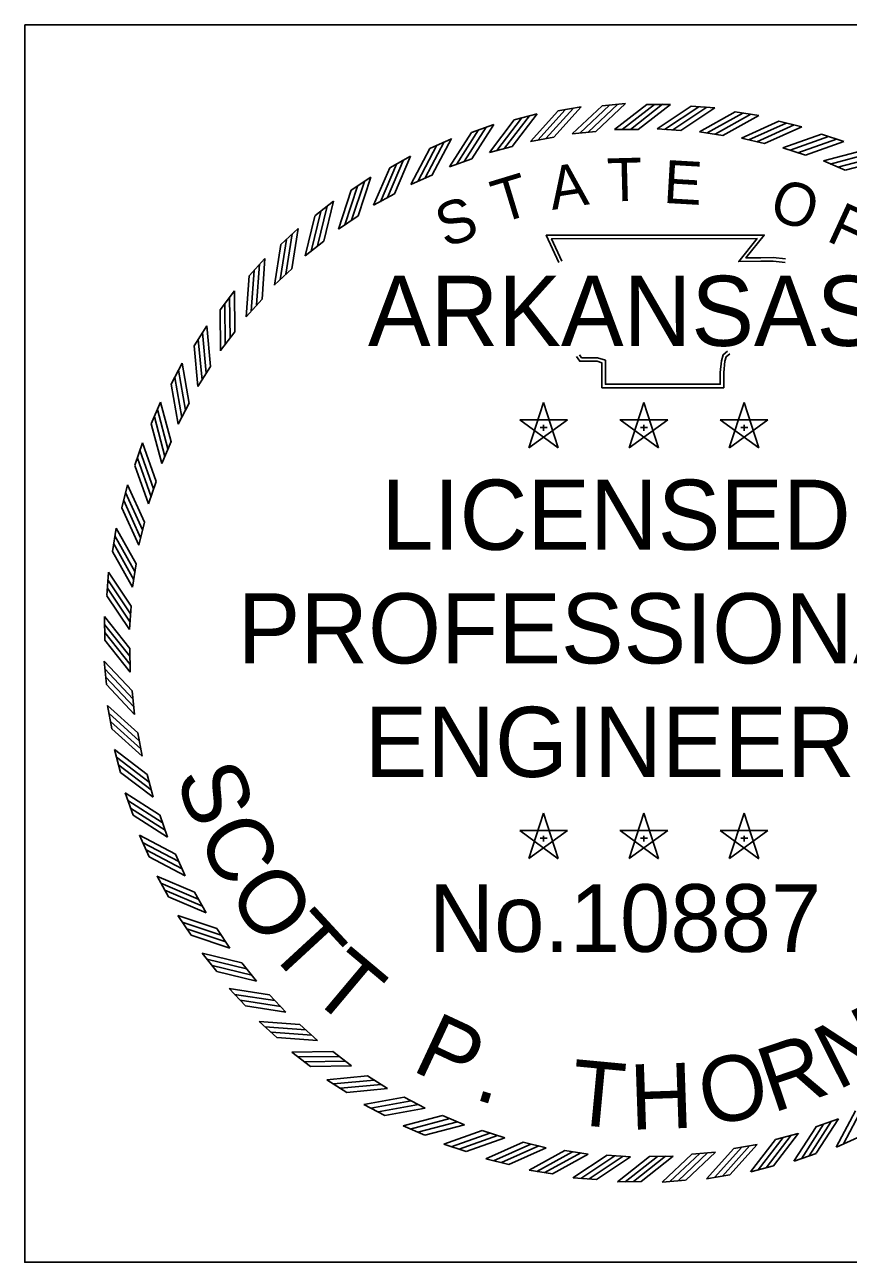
# Model space of a CAD drawing. Extents: x 164 to 3385, y 68 to 2119.
# Drawn here: x 3004.1 to 3177.5, y 441.7 to 702.4 of the extents above; entities that cross this region are included whole.
import ezdxf

# ---------------------------------------------------------------- set-up
doc = ezdxf.new("R2010")
doc.units = 0
doc.layers.add('R_No Plot', color=7, linetype='Continuous')
doc.layers.add('STAMP', color=7, linetype='Continuous')

msp = doc.modelspace()

# ---------------------------------------------------------------- linework, layer by layer
at = {"layer": 'R_No Plot'}
msp.add_lwpolyline([(3004.12, 702.45), (3264.86, 702.45), (3264.86, 441.7), (3004.12, 441.7)], close=True, dxfattribs=at)
at = {"layer": 'STAMP'}
for p, q in [((3125.7, 685.39), (3130.65, 685.85)), ((3107.19, 682.4), (3112, 683.67)), ((3116.38, 684.28), (3121.28, 685.14)), ((3135.12, 685.67), (3140.1, 685.67)), ((3144.45, 685.3), (3149.42, 684.94)), ((3144.45, 685.3), (3149.41, 684.93)), ((3153.75, 684.09), (3158.67, 683.31)), ((3098.18, 679.77), (3102.87, 681.43)), ((3162.93, 682.12), (3167.76, 680.94)), ((3089.42, 676.4), (3093.96, 678.44)), ((3110.61, 677.88), (3115.52, 678.75)), ((3119.42, 679.49), (3124.39, 679.95)), ((3128.33, 680.37), (3133.32, 680.37)), ((3137.28, 680.51), (3142.26, 680.15)), ((3137.28, 680.51), (3142.26, 680.15)), ((3146.22, 679.91), (3151.15, 679.14)), ((3155.07, 678.58), (3159.92, 677.4)), ((3171.9, 679.39), (3176.63, 677.82)), ((3101.97, 675.55), (3106.79, 676.82)), ((3163.79, 676.51), (3168.52, 674.94)), ((3080.97, 672.33), (3085.33, 674.73)), ((3093.54, 672.51), (3098.25, 674.17)), ((3172.3, 673.74), (3176.89, 671.78)), ((3072.89, 667.56), (3077.03, 670.32)), ((3085.4, 668.79), (3089.95, 670.83)), ((3065.22, 662.15), (3069.12, 665.24)), ((3077.59, 664.4), (3081.96, 666.82)), ((3070.17, 659.39), (3074.32, 662.16)), ((3058.03, 656.12), (3061.66, 659.53)), ((3063.19, 653.78), (3067.1, 656.88)), ((3051.36, 649.52), (3054.7, 653.21)), ((3056.7, 647.61), (3060.34, 651.02)), ((3045.26, 642.39), (3048.28, 646.35)), ((3050.74, 640.93), (3054.08, 644.63)), ((3039.77, 634.78), (3042.46, 638.98)), ((3045.35, 633.78), (3048.38, 637.74)), ((3034.93, 626.75), (3037.26, 631.15)), ((3040.57, 626.21), (3043.26, 630.41)), ((3030.76, 618.34), (3032.72, 622.92)), ((3036.43, 618.27), (3038.76, 622.68)), ((3113.37, 622.87), (3110.26, 613.31)), ((3116.47, 613.32), (3113.38, 622.88)), ((3134.49, 622.87), (3131.37, 613.31)), ((3137.59, 613.32), (3134.49, 622.88)), ((3155.6, 622.87), (3152.48, 613.31)), ((3158.7, 613.32), (3155.61, 622.88)), ((3118.39, 619.22), (3108.34, 619.23)), ((3108.35, 619.22), (3116.48, 613.3)), ((3110.27, 613.32), (3118.4, 619.22)), ((3113.38, 618.15), (3113.38, 616.89)), ((3139.51, 619.22), (3129.46, 619.23)), ((3129.47, 619.22), (3137.59, 613.3)), ((3131.38, 613.32), (3139.52, 619.22)), ((3134.49, 618.15), (3134.49, 616.89)), ((3160.62, 619.22), (3150.57, 619.23)), ((3150.58, 619.22), (3158.7, 613.3)), ((3152.5, 613.32), (3160.63, 619.22)), ((3155.61, 618.15), (3155.61, 616.89)), ((3112.66, 617.61), (3114.15, 617.61)), ((3133.77, 617.61), (3135.26, 617.61)), ((3154.88, 617.61), (3156.38, 617.61)), ((3027.31, 609.62), (3028.88, 614.34)), ((3032.96, 610.01), (3034.92, 614.6)), ((3024.58, 600.64), (3025.76, 605.47)), ((3030.19, 601.5), (3031.76, 606.23)), ((3028.12, 592.78), (3029.3, 597.63)), ((3022.61, 591.46), (3023.39, 596.38)), ((3021.4, 582.16), (3021.77, 587.12)), ((3026.79, 583.93), (3027.56, 588.86)), ((3026.19, 574.99), (3026.55, 579.97)), ((3020.97, 572.79), (3020.92, 577.76)), ((3026.33, 566.04), (3026.28, 571.03)), ((3021.31, 563.41), (3020.85, 568.36)), ((3027.21, 557.13), (3026.75, 562.1)), ((3022.42, 554.09), (3021.56, 558.99)), ((3028.82, 548.32), (3027.95, 553.24)), ((3024.3, 544.9), (3023.03, 549.71)), ((3031.15, 539.68), (3029.88, 544.5)), ((3026.93, 535.89), (3025.27, 540.58)), ((3034.19, 531.25), (3032.53, 535.96)), ((3113.37, 536.29), (3110.26, 526.74)), ((3116.47, 526.75), (3113.38, 536.31)), ((3134.49, 536.29), (3131.37, 526.74)), ((3137.59, 526.75), (3134.49, 536.31)), ((3155.6, 536.29), (3152.48, 526.74)), ((3158.7, 526.75), (3155.61, 536.31)), ((3118.39, 532.65), (3108.34, 532.66)), ((3108.35, 532.65), (3116.48, 526.73)), ((3110.27, 526.75), (3118.4, 532.64)), ((3139.51, 532.65), (3129.46, 532.66)), ((3129.47, 532.65), (3137.59, 526.73)), ((3131.38, 526.75), (3139.52, 532.64)), ((3160.62, 532.65), (3150.57, 532.66)), ((3150.58, 532.65), (3158.7, 526.73)), ((3152.5, 526.75), (3160.63, 532.64)), ((3030.3, 527.13), (3028.26, 531.67)), ((3112.66, 531.04), (3114.15, 531.04)), ((3113.38, 531.58), (3113.38, 530.32)), ((3133.77, 531.04), (3135.26, 531.04)), ((3134.49, 531.58), (3134.49, 530.32)), ((3154.88, 531.04), (3156.38, 531.04)), ((3155.61, 531.58), (3155.61, 530.32)), ((3037.91, 523.11), (3035.87, 527.66)), ((3034.38, 518.68), (3031.97, 523.04)), ((3042.3, 515.3), (3039.88, 519.67)), ((3039.14, 510.6), (3036.38, 514.74)), ((3047.31, 507.88), (3044.55, 512.03)), ((3044.55, 502.93), (3041.46, 506.83)), ((3052.92, 500.9), (3049.82, 504.81)), ((3050.58, 495.74), (3047.17, 499.37)), ((3059.09, 494.41), (3055.68, 498.05)), ((3057.18, 489.07), (3053.49, 492.41)), ((3065.77, 488.45), (3062.07, 491.79)), ((3064.31, 482.97), (3060.35, 485.99)), ((3072.92, 483.06), (3068.96, 486.09)), ((3071.92, 477.48), (3067.72, 480.17)), ((3080.49, 478.28), (3076.29, 480.97)), ((3079.95, 472.64), (3075.55, 474.97)), ((3088.43, 474.14), (3084.02, 476.48)), ((3096.69, 470.67), (3092.1, 472.63)), ((3088.36, 468.47), (3083.78, 470.43)), ((3105.2, 467.9), (3100.47, 469.47)), ((3175.45, 471.9), (3170.74, 470.24)), ((3113.92, 465.84), (3109.07, 467.02)), ((3167.02, 468.86), (3162.2, 467.59)), ((3179.57, 468.01), (3175.03, 465.97)), ((3097.08, 465.02), (3092.36, 466.59)), ((3122.77, 464.5), (3117.84, 465.28)), ((3131.71, 463.9), (3126.73, 464.27)), ((3149.57, 464.92), (3144.6, 464.46)), ((3158.38, 466.53), (3153.47, 465.66)), ((3170.81, 464.64), (3166.12, 462.98)), ((3106.06, 462.3), (3101.23, 463.47)), ((3140.66, 464.04), (3135.67, 463.99)), ((3161.8, 462.01), (3156.99, 460.74)), ((3115.24, 460.32), (3110.32, 461.1)), ((3124.54, 459.12), (3119.58, 459.48)), ((3143.29, 459.02), (3138.34, 458.56)), ((3152.61, 460.13), (3147.71, 459.27)), ((3133.92, 458.68), (3128.94, 458.63))]:
    msp.add_line(p, q, dxfattribs=at)
for points in [[(3124.38, 679.96), (3130.66, 685.85)], [(3105.18, 676.41), (3110.4, 683.26)], [(3106.78, 676.82), (3112, 683.67)], [(3110.61, 677.88), (3116.37, 684.27)], [(3112.19, 678.14), (3117.95, 684.54)], [(3113.88, 678.48), (3119.65, 684.88)], [(3115.52, 678.75), (3121.29, 685.15)], [(3119.41, 679.49), (3125.69, 685.39)], [(3121.01, 679.62), (3127.29, 685.52)], [(3122.73, 679.82), (3129.01, 685.72)], [(3128.32, 680.37), (3135.12, 685.67)], [(3129.93, 680.35), (3136.72, 685.65)], [(3131.66, 680.39), (3138.45, 685.69)], [(3133.31, 680.38), (3140.11, 685.67)], [(3137.27, 680.51), (3144.44, 685.3)], [(3137.28, 680.51), (3144.44, 685.29)], [(3138.87, 680.38), (3146.04, 685.17)], [(3138.87, 680.38), (3146.04, 685.16)], [(3140.6, 680.29), (3147.77, 685.08)], [(3140.6, 680.29), (3147.76, 685.07)], [(3142.25, 680.15), (3149.42, 684.94)], [(3142.25, 680.15), (3149.42, 684.93)], [(3146.21, 679.91), (3153.74, 684.09)], [(3147.79, 679.65), (3155.32, 683.82)], [(3149.51, 679.41), (3157.04, 683.59)], [(3151.14, 679.14), (3158.67, 683.32)], [(3096.67, 673.64), (3101.31, 680.9)], [(3098.24, 674.18), (3102.88, 681.43)], [(3101.96, 675.54), (3107.18, 682.39)], [(3103.51, 675.94), (3108.73, 682.79)], [(3155.07, 678.57), (3162.92, 682.11)], [(3156.62, 678.18), (3164.47, 681.72)], [(3158.31, 677.81), (3166.16, 681.35)], [(3159.92, 677.4), (3167.77, 680.94)], [(3089.94, 670.83), (3093.96, 678.45)], [(3093.54, 672.5), (3098.18, 679.76)], [(3095.05, 673.02), (3099.69, 680.28)], [(3163.78, 676.51), (3171.9, 679.39)], [(3165.29, 675.99), (3173.41, 678.87)], [(3166.95, 675.48), (3175.06, 678.36)], [(3085.4, 668.78), (3089.42, 676.4)], [(3086.86, 669.42), (3090.88, 677.04)], [(3088.42, 670.17), (3092.45, 677.78)], [(3168.52, 674.94), (3176.63, 677.82)], [(3172.29, 673.74), (3180.62, 675.94)], [(3079, 665.16), (3082.38, 673.08)], [(3080.49, 666.03), (3083.87, 673.95)], [(3081.95, 666.82), (3085.33, 674.74)], [(3173.76, 673.09), (3182.09, 675.29)], [(3175.36, 672.45), (3183.69, 674.65)], [(3176.88, 671.78), (3185.21, 673.98)], [(3074.32, 662.16), (3077.03, 670.33)], [(3077.59, 664.4), (3080.97, 672.32)], [(3070.17, 659.38), (3072.88, 667.56)], [(3071.51, 660.26), (3074.22, 668.43)], [(3072.93, 661.25), (3075.64, 669.42)], [(3067.09, 656.88), (3069.12, 665.25)], [(3064.45, 654.76), (3066.48, 663.13)], [(3065.79, 655.86), (3067.81, 664.23)], [(3063.19, 653.77), (3065.22, 662.14)], [(3057.88, 648.69), (3059.21, 657.2)], [(3059.11, 649.9), (3060.44, 658.41)], [(3060.33, 651.02), (3061.66, 659.53)], [(3116.58, 652.36), (3113.92, 658.1), (3159.83, 658.13), (3156, 653.31), (3159.11, 653.35), (3161.72, 653.38), (3164.32, 653.1)], [(3117.24, 652.66), (3115.06, 657.37), (3158.32, 657.4), (3154.47, 652.56), (3159.12, 652.62), (3161.69, 652.66), (3164.24, 652.38)], [(3056.7, 647.6), (3058.03, 656.11)], [(3052.95, 643.41), (3053.58, 652)], [(3054.08, 644.63), (3054.7, 653.22)], [(3050.74, 640.92), (3051.36, 649.51)], [(3051.82, 642.1), (3052.45, 650.69)], [(3047.35, 636.43), (3047.26, 645.05)], [(3048.37, 637.74), (3048.28, 646.35)], [(3045.35, 633.77), (3045.26, 642.38)], [(3046.33, 635.04), (3046.25, 643.65)], [(3043.25, 630.41), (3042.45, 638.98)], [(3042.35, 629.02), (3041.55, 637.59)], [(3040.57, 626.2), (3039.77, 634.78)], [(3041.45, 627.54), (3040.65, 636.12)], [(3152.14, 633.68), (3151.18, 632.9), (3150.84, 631.66), (3150.57, 629.19), (3150.57, 626.7), (3126.4, 626.7), (3126.4, 630.26), (3126.4, 631.75), (3124.74, 632.25), (3121.38, 632.25), (3120.94, 632.91)], [(3038.76, 622.67), (3037.25, 631.15)], [(3152.6, 633.12), (3151.82, 632.48), (3151.56, 631.53), (3151.3, 629.15), (3151.3, 625.97), (3125.67, 625.97), (3125.67, 630.26), (3125.67, 631.21), (3124.63, 631.53), (3120.98, 631.53), (3120.34, 632.52)], [(3037.97, 621.21), (3036.47, 629.69)], [(3036.43, 618.26), (3034.93, 626.74)], [(3037.19, 619.67), (3035.69, 628.15)], [(3034.25, 613.08), (3032.05, 621.4)], [(3034.92, 614.59), (3032.72, 622.92)], [(3032.96, 610), (3030.76, 618.33)], [(3033.61, 611.47), (3031.41, 619.8)], [(3031.22, 604.66), (3028.34, 612.78)], [(3031.76, 606.23), (3028.88, 614.34)], [(3030.71, 603.01), (3027.83, 611.12)], [(3030.19, 601.49), (3027.31, 609.61)], [(3029.3, 597.63), (3025.76, 605.48)], [(3028.89, 596.02), (3025.35, 603.87)], [(3028.13, 592.78), (3024.59, 600.63)], [(3028.52, 594.33), (3024.98, 602.18)], [(3027.29, 587.22), (3023.11, 594.75)], [(3027.56, 588.85), (3023.38, 596.39)], [(3027.06, 585.5), (3022.88, 593.04)], [(3026.79, 583.92), (3022.62, 591.46)], [(3026.55, 579.97), (3021.77, 587.13)], [(3026.41, 578.31), (3021.63, 585.47)], [(3026.19, 574.99), (3021.41, 582.15)], [(3026.32, 576.59), (3021.54, 583.75)], [(3026.28, 571.02), (3020.92, 577.77)], [(3026.28, 569.37), (3020.92, 576.11)], [(3026.33, 567.64), (3020.97, 574.38)], [(3026.33, 566.04), (3020.97, 572.78)], [(3026.75, 562.09), (3020.85, 568.37)], [(3026.88, 560.44), (3020.98, 566.72)], [(3027.08, 558.72), (3021.18, 565)], [(3027.21, 557.12), (3021.31, 563.4)], [(3027.95, 553.23), (3021.55, 559)], [(3028.22, 551.59), (3021.83, 557.36)], [(3028.56, 549.9), (3022.16, 555.67)], [(3028.82, 548.32), (3022.43, 554.09)], [(3029.88, 544.5), (3023.03, 549.72)], [(3030.29, 542.89), (3023.44, 548.11)], [(3030.76, 541.23), (3023.91, 546.45)], [(3031.16, 539.67), (3024.31, 544.89)], [(3032.52, 535.95), (3025.27, 540.59)], [(3033.06, 534.38), (3025.81, 539.02)], [(3033.68, 532.76), (3026.42, 537.4)], [(3034.2, 531.25), (3026.94, 535.89)], [(3035.87, 527.65), (3028.25, 531.68)], [(3036.53, 526.14), (3028.92, 530.16)], [(3037.28, 524.57), (3029.66, 528.6)], [(3037.92, 523.11), (3030.3, 527.13)], [(3039.88, 519.66), (3031.96, 523.04)], [(3040.67, 518.2), (3032.75, 521.58)], [(3041.54, 516.71), (3033.62, 520.09)], [(3042.31, 515.3), (3034.38, 518.68)], [(3044.55, 512.03), (3036.37, 514.74)], [(3045.45, 510.64), (3037.28, 513.35)], [(3046.44, 509.22), (3038.27, 511.94)], [(3047.32, 507.88), (3039.15, 510.59)], [(3049.82, 504.81), (3041.45, 506.83)], [(3050.84, 503.5), (3042.47, 505.53)], [(3051.95, 502.17), (3043.57, 504.2)], [(3052.93, 500.9), (3044.56, 502.93)], [(3055.68, 498.04), (3047.17, 499.37)], [(3056.8, 496.82), (3048.29, 498.15)], [(3058.01, 495.59), (3049.5, 496.92)], [(3059.1, 494.41), (3050.59, 495.74)], [(3062.07, 491.79), (3053.48, 492.41)], [(3063.29, 490.67), (3054.7, 491.29)], [(3064.6, 489.53), (3056.01, 490.16)], [(3065.78, 488.45), (3057.19, 489.07)], [(3068.96, 486.08), (3060.35, 485.99)], [(3070.27, 485.06), (3061.65, 484.98)], [(3071.66, 484.04), (3063.05, 483.96)], [(3072.93, 483.06), (3064.32, 482.97)], [(3076.29, 480.96), (3067.72, 480.17)], [(3077.68, 480.06), (3069.11, 479.26)], [(3079.16, 479.16), (3070.58, 478.36)], [(3080.5, 478.28), (3071.93, 477.48)], [(3084.03, 476.47), (3075.55, 474.97)], [(3085.49, 475.68), (3077.01, 474.18)], [(3087.03, 474.91), (3078.55, 473.4)], [(3088.44, 474.14), (3079.96, 472.64)], [(3092.11, 472.63), (3083.78, 470.43)], [(3093.62, 471.96), (3085.3, 469.76)], [(3179.05, 473.58), (3175.02, 465.96)], [(3180.57, 474.24), (3176.54, 466.63)], [(3095.23, 471.32), (3086.9, 469.12)], [(3096.7, 470.67), (3088.37, 468.48)], [(3100.47, 469.47), (3092.36, 466.59)], [(3170.75, 470.24), (3166.11, 462.98)], [(3172.32, 470.77), (3167.68, 463.52)], [(3173.94, 471.39), (3169.3, 464.13)], [(3175.45, 471.91), (3170.81, 464.65)], [(3102.04, 468.93), (3093.93, 466.05)], [(3103.69, 468.42), (3095.58, 465.54)], [(3105.21, 467.9), (3097.09, 465.02)], [(3109.07, 467.01), (3101.22, 463.47)], [(3162.21, 467.59), (3156.98, 460.74)], [(3163.81, 468), (3158.59, 461.15)], [(3165.48, 468.47), (3160.25, 461.62)], [(3167.03, 468.87), (3161.81, 462.02)], [(3110.68, 466.6), (3102.83, 463.06)], [(3112.37, 466.23), (3104.52, 462.69)], [(3113.92, 465.84), (3106.07, 462.3)], [(3117.85, 465.27), (3110.32, 461.09)], [(3119.48, 465), (3111.95, 460.82)], [(3121.2, 464.77), (3113.66, 460.59)], [(3122.78, 464.5), (3115.25, 460.33)], [(3126.74, 464.26), (3119.57, 459.48)], [(3144.61, 464.46), (3138.33, 458.56)], [(3146.26, 464.59), (3139.98, 458.7)], [(3147.98, 464.79), (3141.7, 458.89)], [(3149.58, 464.92), (3143.3, 459.02)], [(3153.47, 465.66), (3147.7, 459.26)], [(3155.11, 465.93), (3149.34, 459.54)], [(3156.8, 466.27), (3151.04, 459.87)], [(3158.38, 466.53), (3152.62, 460.14)], [(3128.39, 464.12), (3121.23, 459.34)], [(3130.12, 464.04), (3122.95, 459.25)], [(3131.71, 463.9), (3124.55, 459.12)], [(3135.68, 463.99), (3128.93, 458.63)], [(3137.33, 463.99), (3130.59, 458.63)], [(3139.06, 464.04), (3132.32, 458.68)], [(3140.66, 464.04), (3133.92, 458.68)]]:
    msp.add_lwpolyline(points, dxfattribs=at)

# ---------------------------------------------------------------- texts
for s, height, rotation, p in [('A', 9.06, 8.6788, (3115.18, 663.41)), ('T', 9.07, 1.4789, (3126.85, 665.19)), ('T', 9.06, 1.4789, (3126.87, 665.21)), ('E', 9.06, 356.672, (3138.46, 664.93)), ('T', 9.06, 16.9015, (3104.18, 660.54)), ('O', 9.06, 341.2218, (3160.45, 661.83)), ('S', 9.06, 19.7726, (3092.67, 655.37)), ('F', 9.06, 335.3628, (3172.65, 657.06)), ('S', 13.75, 289.7007, (3035.77, 544.11)), ('C', 13.75, 296.9967, (3040.19, 531.76)), ('O', 13.75, 304.6575, (3046.48, 519.51)), ('T', 13.75, 312.6831, (3054.76, 507.7)), ('T', 13.75, 319.9791, (3063.65, 498.06)), ('P', 13.75, 334.9359, (3085.31, 482.22)), ('N', 13.75, 26.7376, (3175.25, 477.81)), ('R', 13.75, 18.712, (3161.61, 473.09)), ('O', 13.75, 10.6864, (3147.46, 470.33)), ('T', 13.75, 354.6351, (3118.68, 470.82)), ('H', 13.75, 1.9312, (3131.74, 469.6)), ('.', 13.75, 342.9615, (3098.41, 476.19))]:
    msp.add_text(s, height=height, rotation=rotation, dxfattribs=at).set_placement(p)
for s, height, p in [('ARKANSAS', 14.78, (3076.4, 634.77)), ('LICENSED', 14.78, (3079.21, 591.81)), ('PROFESSIONAL', 14.7798, (3048.95, 567.88)), ('ENGINEER', 14.78, (3075.69, 543.95)), ('No.10887', 14.252, (3089.2, 507.1))]:
    msp.add_text(s, height=height, dxfattribs=at).set_placement(p)

doc.saveas('drawing.dxf')
